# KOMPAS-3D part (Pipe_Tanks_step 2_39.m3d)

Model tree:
1. X Axis
2. Y Axis
3. Z Axis  (labels: Pipe Dn 50; Valve Dy 50)
     Òîëùèíà ñòåíêè 1 = 1

Referenced files in C:\Documents and Settings\kashirsky\Мои документы\Camtasia Studio\Pipelines3D\Tanks\: Tanks_step 2.a3d
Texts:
  Pipe Dn 50
  Steel ASTM A295
  Three Point Plane
  Plane at Angle
  Line and Point Plane
  Axis through Two Vertices
  Axis of Feature
  Axis of Conical Surface
  Axis through Edge
  Trim by Surface
  Trim by Sketch
  Feature with No History
  Intersection Axis of Two Planes
  Two Line Plane
  Line and Face Plane
  Bend by line
  Hole in sheet body
  Cut in sheet body
  Point in CM
  Linear Dimension from Line to Point
  Surface Finish Symbol
  Geometric Tolerance Symbol
  Leader #1
  Leader #2
  Leader #3
  Shape Deviations and Datum
  Node point number
  Mark of coordination axis
  Node point designation
  Mark/Reference designation with leader
  Mark/reference designation on line
  Mark/Reference designation without leader
  Valve Dy 50
  Plane of section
